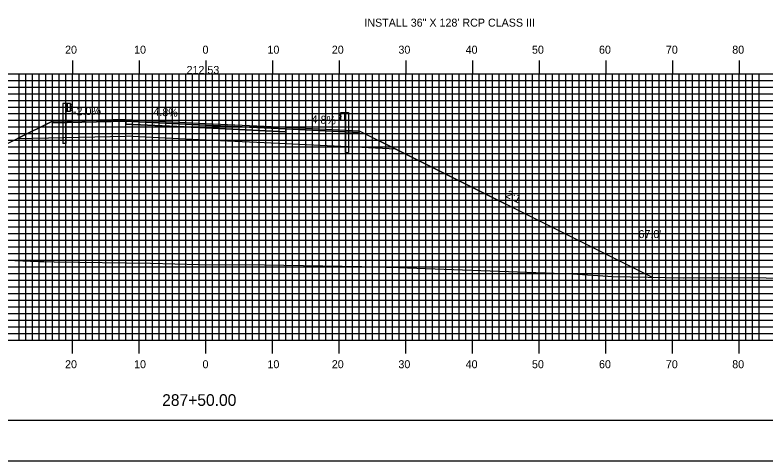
# Model space of a CAD drawing. Extents: x 1812948 to 1813291, y 442591 to 442811.
# Drawn here: x 1813084.9 to 1813197.3, y 442590.5 to 442657.5 of the extents above; entities that cross this region are included whole.
import ezdxf

# ---------------------------------------------------------------- set-up
doc = ezdxf.new("R2010")
doc.units = 0
for name, color, linetype in [('ANNOTATION', 7, 'Continuous'), ('BORDER', 7, 'Continuous'), ('D_Guardrail_Beam_Lt', 7, 'Continuous'), ('D_Guardrail_Beam_Rt', 7, 'Continuous'), ('D_Roadway_Centerline', 7, 'Continuous'), ('D_Roadway_Centerline_Text', 7, 'Continuous'), ('D_Roadway_Edge_Shoulder', 7, 'Continuous'), ('D_Roadway_Edge_TW', 7, 'Continuous'), ('D_Roadway_Pavement', 7, 'Continuous'), ('D_Roadway_SlopeLines', 7, 'Continuous'), ('D_Roadway_SubGrade', 7, 'Continuous'), ('D_Text_Standard', 7, 'Continuous'), ('H_V ANNOTATION', 7, 'Continuous'), ('MAJOR', 7, 'Continuous'), ('MINOR', 7, 'Continuous'), ('PLOT BOUNDARY', 7, 'Continuous'), ('S_Roadway_Centerline', 7, 'Continuous')]:
    doc.layers.add(name, color=color, linetype=linetype)

msp = doc.modelspace()

# ---------------------------------------------------------------- linework, layer by layer
at = {"layer": 'BORDER'}
msp.add_lwpolyline([(1812963.86, 442596.67), (1813283.86, 442596.67), (1813283.86, 442806.67), (1812963.86, 442806.67)], close=True, dxfattribs=at)
at = {"layer": 'D_Guardrail_Beam_Lt'}
for p, q in [((1813092.03, 442644.2), (1813092.03, 442638.2)), ((1813092.5, 442644.2), (1813092.03, 442644.2)), ((1813093.18, 442644.2), (1813092.5, 442644.2)), ((1813092.5, 442644.2), (1813092.5, 442643.03)), ((1813092.56, 442644.2), (1813092.56, 442643.03)), ((1813092.66, 442644.2), (1813092.66, 442643.03)), ((1813093.18, 442643.03), (1813093.18, 442644.2)), ((1813093.18, 442644.11), (1813093.26, 442644.1)), ((1813093.27, 442644.09), (1813093.42, 442643.99)), ((1813092.5, 442643.03), (1813093.18, 442643.03)), ((1813092.52, 442638.2), (1813092.52, 442643.03)), ((1813093.26, 442643.13), (1813093.18, 442643.11)), ((1813093.19, 442643.65), (1813093.19, 442643.58)), ((1813093.42, 442643.85), (1813093.22, 442643.71)), ((1813093.22, 442643.52), (1813093.42, 442643.38)), ((1813093.42, 442643.24), (1813093.27, 442643.14)), ((1813092.52, 442638.2), (1813092.03, 442638.2))]:
    msp.add_line(p, q, dxfattribs=at)
for centre, major_axis, start_param, end_param in [((1813093.25, 442644.06), (0.0417, 0), 0.959931, 1.376053), ((1813093.27, 442643.65), (-0.0789, 0), 5.323254, 6.283185), ((1813093.27, 442643.58), (-0.0789, 0), 6.283185, 7.243116), ((1813093.25, 442643.17), (0.0417, 0), 4.907132, 5.323254), ((1813093.37, 442643.92), (0.0877, 0), 5.323254, 7.243116), ((1813093.37, 442643.31), (0.0877, 0), 5.323254, 7.243116)]:
    msp.add_ellipse(centre, major_axis=major_axis, ratio=0.995501, start_param=start_param, end_param=end_param, dxfattribs=at)
at = {"layer": 'D_Guardrail_Beam_Rt'}
for p, q in [((1813133.64, 442642.72), (1813133.49, 442642.62)), ((1813133.49, 442642.47), (1813133.69, 442642.34)), ((1813133.69, 442642.14), (1813133.49, 442642)), ((1813133.49, 442641.86), (1813133.64, 442641.76)), ((1813133.73, 442642.74), (1813133.65, 442642.72)), ((1813133.65, 442641.75), (1813133.73, 442641.74)), ((1813133.72, 442642.27), (1813133.72, 442642.2)), ((1813133.73, 442642.82), (1813134.41, 442642.82)), ((1813133.73, 442641.66), (1813133.73, 442642.82)), ((1813134.25, 442642.82), (1813134.25, 442641.66)), ((1813134.35, 442642.82), (1813134.35, 442641.66)), ((1813134.41, 442642.82), (1813134.88, 442642.82)), ((1813134.41, 442642.82), (1813134.41, 442641.66)), ((1813134.88, 442642.82), (1813134.88, 442636.82)), ((1813134.41, 442641.66), (1813133.73, 442641.66)), ((1813134.39, 442636.82), (1813134.39, 442641.66)), ((1813134.39, 442636.82), (1813134.88, 442636.82))]:
    msp.add_line(p, q, dxfattribs=at)
for centre, major_axis, start_param, end_param in [((1813133.54, 442642.55), (-0.0877, 0), 5.323254, 7.243116), ((1813133.54, 442641.93), (-0.0877, 0), 5.323254, 7.243116), ((1813133.66, 442642.68), (-0.0417, 0), 4.907132, 5.323254), ((1813133.66, 442641.79), (-0.0417, 0), 0.959931, 1.376053), ((1813133.64, 442642.27), (0.0789, 0), 0, 0.959931), ((1813133.64, 442642.2), (0.0789, 0), 5.323254, 6.283185)]:
    msp.add_ellipse(centre, major_axis=major_axis, ratio=0.995501, start_param=start_param, end_param=end_param, dxfattribs=at)
at = {"layer": 'D_Roadway_Centerline'}
msp.add_lwpolyline([(1813053.59, 442623.12), (1813085.25, 442638.95), (1813090.46, 442641.55), (1813093.46, 442641.61), (1813101.46, 442641.77), (1813113.46, 442641.2), (1813125.46, 442640.62), (1813133.46, 442640.24), (1813136.46, 442640.09), (1813141.99, 442637.33), (1813180.41, 442618.12)], dxfattribs=at)
at = {"layer": 'D_Roadway_Edge_Shoulder'}
for points in [[(1813101.46, 442641.77), (1813093.46, 442641.61), (1813093.46, 442641.61), (1813090.46, 442641.55), (1813090.46, 442641.3), (1813101.46, 442641.52)], [(1813125.46, 442640.62), (1813133.46, 442640.24), (1813133.46, 442640.24), (1813136.46, 442640.09), (1813136.46, 442639.84), (1813125.46, 442640.37)]]:
    msp.add_lwpolyline(points, close=True, dxfattribs=at)
at = {"layer": 'D_Roadway_Edge_TW'}
msp.add_lwpolyline([(1813101.46, 442641.52), (1813101.46, 442641.77), (1813113.46, 442641.2), (1813125.46, 442640.62), (1813125.46, 442640.37), (1813113.46, 442640.95)], close=True, dxfattribs=at)
at = {"layer": 'D_Roadway_Pavement'}
msp.add_lwpolyline([(1813101.46, 442641.11), (1813101.46, 442641.52), (1813113.46, 442640.95), (1813125.46, 442640.37), (1813125.46, 442639.96), (1813113.46, 442640.53)], close=True, dxfattribs=at)
for points in [[(1813101.46, 442641.52), (1813101.46, 442641.11)], [(1813125.46, 442640.37), (1813125.46, 442639.96)]]:
    msp.add_lwpolyline(points, dxfattribs=at)
at = {"layer": 'D_Roadway_SlopeLines'}
for points in [[(1813090.46, 442641.55), (1813053.59, 442623.12)], [(1813136.46, 442640.09), (1813180.41, 442618.12)]]:
    msp.add_lwpolyline(points, dxfattribs=at)
at = {"layer": 'D_Roadway_SubGrade'}
for points in [[(1813101.46, 442641.11), (1813101.46, 442641.52), (1813090.46, 442641.3), (1813090.46, 442641.55), (1813085.25, 442638.95), (1813101.46, 442639.27)], [(1813101.46, 442639.27), (1813101.46, 442641.52), (1813101.46, 442641.11), (1813113.46, 442640.53), (1813125.46, 442639.96), (1813125.46, 442640.37), (1813125.46, 442638.12), (1813113.46, 442638.7)], [(1813125.46, 442639.96), (1813125.46, 442640.37), (1813136.46, 442639.84), (1813136.46, 442640.09), (1813141.99, 442637.33), (1813125.46, 442638.12)]]:
    msp.add_lwpolyline(points, close=True, dxfattribs=at)
at = {"layer": 'MAJOR'}
for p, q in [((1813093.46, 442650.67), (1813093.46, 442648.67)), ((1813103.46, 442650.67), (1813103.46, 442648.67)), ((1813113.46, 442650.67), (1813113.46, 442648.67)), ((1813123.46, 442650.67), (1813123.46, 442648.67)), ((1813133.46, 442650.67), (1813133.46, 442648.67)), ((1813143.46, 442650.67), (1813143.46, 442648.67)), ((1813153.46, 442650.67), (1813153.46, 442648.67)), ((1813163.46, 442650.67), (1813163.46, 442648.67)), ((1813173.46, 442650.67), (1813173.46, 442648.67)), ((1813183.46, 442650.67), (1813183.46, 442648.67)), ((1813193.46, 442650.67), (1813193.46, 442648.67)), ((1812973.46, 442648.67), (1813253.46, 442648.67)), ((1812973.46, 442648.67), (1813253.46, 442648.67)), ((1813093.46, 442608.67), (1813093.46, 442648.67)), ((1813103.46, 442608.67), (1813103.46, 442648.67)), ((1813113.46, 442608.67), (1813113.46, 442648.67)), ((1813123.46, 442608.67), (1813123.46, 442648.67)), ((1813133.46, 442608.67), (1813133.46, 442648.67)), ((1813143.46, 442608.67), (1813143.46, 442648.67)), ((1813153.46, 442608.67), (1813153.46, 442648.67)), ((1813163.46, 442608.67), (1813163.46, 442648.67)), ((1813173.46, 442608.67), (1813173.46, 442648.67)), ((1813183.46, 442608.67), (1813183.46, 442648.67)), ((1813193.46, 442608.67), (1813193.46, 442648.67)), ((1812973.46, 442643.67), (1813253.46, 442643.67)), ((1812973.46, 442638.67), (1813253.46, 442638.67)), ((1812973.46, 442633.67), (1813253.46, 442633.67)), ((1812973.46, 442628.67), (1813253.46, 442628.67)), ((1812973.46, 442623.67), (1813253.46, 442623.67)), ((1812973.46, 442618.67), (1813253.46, 442618.67)), ((1812973.46, 442613.67), (1813253.46, 442613.67)), ((1812973.46, 442608.67), (1813253.46, 442608.67)), ((1812973.46, 442608.67), (1813253.46, 442608.67)), ((1813093.46, 442606.66), (1813093.46, 442608.67)), ((1813103.46, 442606.66), (1813103.46, 442608.67)), ((1813113.46, 442606.66), (1813113.46, 442608.67)), ((1813123.46, 442606.66), (1813123.46, 442608.67)), ((1813133.46, 442606.66), (1813133.46, 442608.67)), ((1813143.46, 442606.66), (1813143.46, 442608.67)), ((1813153.46, 442606.66), (1813153.46, 442608.67)), ((1813163.46, 442606.66), (1813163.46, 442608.67)), ((1813173.46, 442606.66), (1813173.46, 442608.67)), ((1813183.46, 442606.66), (1813183.46, 442608.67)), ((1813193.46, 442606.66), (1813193.46, 442608.67))]:
    msp.add_line(p, q, dxfattribs=at)
at = {"layer": 'MINOR'}
for p, q in [((1813085.46, 442608.67), (1813085.46, 442648.67)), ((1813086.46, 442608.67), (1813086.46, 442648.67)), ((1813087.46, 442608.67), (1813087.46, 442648.67)), ((1813088.46, 442608.67), (1813088.46, 442648.67)), ((1813089.46, 442608.67), (1813089.46, 442648.67)), ((1813090.46, 442608.67), (1813090.46, 442648.67)), ((1813091.46, 442608.67), (1813091.46, 442648.67)), ((1813092.46, 442608.67), (1813092.46, 442648.67)), ((1813094.46, 442608.67), (1813094.46, 442648.67)), ((1813095.46, 442608.67), (1813095.46, 442648.67)), ((1813096.46, 442608.67), (1813096.46, 442648.67)), ((1813097.46, 442608.67), (1813097.46, 442648.67)), ((1813098.46, 442608.67), (1813098.46, 442648.67)), ((1813099.46, 442608.67), (1813099.46, 442648.67)), ((1813100.46, 442608.67), (1813100.46, 442648.67)), ((1813101.46, 442608.67), (1813101.46, 442648.67)), ((1813102.46, 442608.67), (1813102.46, 442648.67)), ((1813104.46, 442608.67), (1813104.46, 442648.67)), ((1813105.46, 442608.67), (1813105.46, 442648.67)), ((1813106.46, 442608.67), (1813106.46, 442648.67)), ((1813107.46, 442608.67), (1813107.46, 442648.67)), ((1813108.46, 442608.67), (1813108.46, 442648.67)), ((1813109.46, 442608.67), (1813109.46, 442648.67)), ((1813110.46, 442608.67), (1813110.46, 442648.67)), ((1813111.46, 442608.67), (1813111.46, 442648.67)), ((1813112.46, 442608.67), (1813112.46, 442648.67)), ((1813114.46, 442608.67), (1813114.46, 442648.67)), ((1813115.46, 442608.67), (1813115.46, 442648.67)), ((1813116.46, 442608.67), (1813116.46, 442648.67)), ((1813117.46, 442608.67), (1813117.46, 442648.67)), ((1813118.46, 442608.67), (1813118.46, 442648.67)), ((1813119.46, 442608.67), (1813119.46, 442648.67)), ((1813120.46, 442608.67), (1813120.46, 442648.67)), ((1813121.46, 442608.67), (1813121.46, 442648.67)), ((1813122.46, 442608.67), (1813122.46, 442648.67)), ((1813124.46, 442608.67), (1813124.46, 442648.67)), ((1813125.46, 442608.67), (1813125.46, 442648.67)), ((1813126.46, 442608.67), (1813126.46, 442648.67)), ((1813127.46, 442608.67), (1813127.46, 442648.67)), ((1813128.46, 442608.67), (1813128.46, 442648.67)), ((1813129.46, 442608.67), (1813129.46, 442648.67)), ((1813130.46, 442608.67), (1813130.46, 442648.67)), ((1813131.46, 442608.67), (1813131.46, 442648.67)), ((1813132.46, 442608.67), (1813132.46, 442648.67)), ((1813134.46, 442608.67), (1813134.46, 442648.67)), ((1813135.46, 442608.67), (1813135.46, 442648.67)), ((1813136.46, 442608.67), (1813136.46, 442648.67)), ((1813137.46, 442608.67), (1813137.46, 442648.67)), ((1813138.46, 442608.67), (1813138.46, 442648.67)), ((1813139.46, 442608.67), (1813139.46, 442648.67)), ((1813140.46, 442608.67), (1813140.46, 442648.67)), ((1813141.46, 442608.67), (1813141.46, 442648.67)), ((1813142.46, 442608.67), (1813142.46, 442648.67)), ((1813144.46, 442608.67), (1813144.46, 442648.67)), ((1813145.46, 442608.67), (1813145.46, 442648.67)), ((1813146.46, 442608.67), (1813146.46, 442648.67)), ((1813147.46, 442608.67), (1813147.46, 442648.67)), ((1813148.46, 442608.67), (1813148.46, 442648.67)), ((1813149.46, 442608.67), (1813149.46, 442648.67)), ((1813150.46, 442608.67), (1813150.46, 442648.67)), ((1813151.46, 442608.67), (1813151.46, 442648.67)), ((1813152.46, 442608.67), (1813152.46, 442648.67)), ((1813154.46, 442608.67), (1813154.46, 442648.67)), ((1813155.46, 442608.67), (1813155.46, 442648.67)), ((1813156.46, 442608.67), (1813156.46, 442648.67)), ((1813157.46, 442608.67), (1813157.46, 442648.67)), ((1813158.46, 442608.67), (1813158.46, 442648.67)), ((1813159.46, 442608.67), (1813159.46, 442648.67)), ((1813160.46, 442608.67), (1813160.46, 442648.67)), ((1813161.46, 442608.67), (1813161.46, 442648.67)), ((1813162.46, 442608.67), (1813162.46, 442648.67)), ((1813164.46, 442608.67), (1813164.46, 442648.67)), ((1813165.46, 442608.67), (1813165.46, 442648.67)), ((1813166.46, 442608.67), (1813166.46, 442648.67)), ((1813167.46, 442608.67), (1813167.46, 442648.67)), ((1813168.46, 442608.67), (1813168.46, 442648.67)), ((1813169.46, 442608.67), (1813169.46, 442648.67)), ((1813170.46, 442608.67), (1813170.46, 442648.67)), ((1813171.46, 442608.67), (1813171.46, 442648.67)), ((1813172.46, 442608.67), (1813172.46, 442648.67)), ((1813174.46, 442608.67), (1813174.46, 442648.67)), ((1813175.46, 442608.67), (1813175.46, 442648.67)), ((1813176.46, 442608.67), (1813176.46, 442648.67)), ((1813177.46, 442608.67), (1813177.46, 442648.67)), ((1813178.46, 442608.67), (1813178.46, 442648.67)), ((1813179.46, 442608.67), (1813179.46, 442648.67)), ((1813180.46, 442608.67), (1813180.46, 442648.67)), ((1813181.46, 442608.67), (1813181.46, 442648.67)), ((1813182.46, 442608.67), (1813182.46, 442648.67)), ((1813184.46, 442608.67), (1813184.46, 442648.67)), ((1813185.46, 442608.67), (1813185.46, 442648.67)), ((1813186.46, 442608.67), (1813186.46, 442648.67)), ((1813187.46, 442608.67), (1813187.46, 442648.67)), ((1813188.46, 442608.67), (1813188.46, 442648.67)), ((1813189.46, 442608.67), (1813189.46, 442648.67)), ((1813190.46, 442608.67), (1813190.46, 442648.67)), ((1813191.46, 442608.67), (1813191.46, 442648.67)), ((1813192.46, 442608.67), (1813192.46, 442648.67)), ((1813194.46, 442608.67), (1813194.46, 442648.67)), ((1813195.46, 442608.67), (1813195.46, 442648.67)), ((1813196.46, 442608.67), (1813196.46, 442648.67)), ((1812973.46, 442647.67), (1813253.46, 442647.67)), ((1812973.46, 442646.67), (1813253.46, 442646.67)), ((1812973.46, 442645.67), (1813253.46, 442645.67)), ((1812973.46, 442644.67), (1813253.46, 442644.67)), ((1812973.46, 442642.67), (1813253.46, 442642.67)), ((1812973.46, 442641.67), (1813253.46, 442641.67)), ((1812973.46, 442640.67), (1813253.46, 442640.67)), ((1812973.46, 442639.67), (1813253.46, 442639.67)), ((1812973.46, 442637.67), (1813253.46, 442637.67)), ((1812973.46, 442636.67), (1813253.46, 442636.67)), ((1812973.46, 442635.67), (1813253.46, 442635.67)), ((1812973.46, 442634.67), (1813253.46, 442634.67)), ((1812973.46, 442632.67), (1813253.46, 442632.67)), ((1812973.46, 442631.67), (1813253.46, 442631.67)), ((1812973.46, 442630.67), (1813253.46, 442630.67)), ((1812973.46, 442629.67), (1813253.46, 442629.67)), ((1812973.46, 442627.67), (1813253.46, 442627.67)), ((1812973.46, 442626.67), (1813253.46, 442626.67)), ((1812973.46, 442625.67), (1813253.46, 442625.67)), ((1812973.46, 442624.67), (1813253.46, 442624.67)), ((1812973.46, 442622.67), (1813253.46, 442622.67)), ((1812973.46, 442621.67), (1813253.46, 442621.67)), ((1812973.46, 442620.67), (1813253.46, 442620.67)), ((1812973.46, 442619.67), (1813253.46, 442619.67)), ((1812973.46, 442617.67), (1813253.46, 442617.67)), ((1812973.46, 442616.67), (1813253.46, 442616.67)), ((1812973.46, 442615.67), (1813253.46, 442615.67)), ((1812973.46, 442614.67), (1813253.46, 442614.67)), ((1812973.46, 442612.67), (1813253.46, 442612.67)), ((1812973.46, 442611.67), (1813253.46, 442611.67)), ((1812973.46, 442610.67), (1813253.46, 442610.67)), ((1812973.46, 442609.67), (1813253.46, 442609.67))]:
    msp.add_line(p, q, dxfattribs=at)
at = {"layer": 'PLOT BOUNDARY'}
msp.add_lwpolyline([(1812947.67, 442590.55), (1813287.67, 442590.55), (1813287.67, 442810.55), (1812947.67, 442810.55)], close=True, dxfattribs=at)
at = {"layer": 'S_Roadway_Centerline'}
msp.add_lwpolyline([(1813084.84, 442620.64), (1813088.36, 442620.5), (1813089.18, 442620.47), (1813090.73, 442620.43), (1813105.15, 442620.24), (1813112.48, 442620.04), (1813122.27, 442620.01), (1813139.78, 442619.7), (1813140.48, 442619.66), (1813141.1, 442619.66), (1813142.38, 442619.6), (1813168.45, 442618.61), (1813174.52, 442618.21), (1813185.03, 442618.05), (1813190.81, 442618.09), (1813204.22, 442618), (1813206.3, 442618.12), (1813207.36, 442618.02), (1813208.86, 442617.96), (1813224.42, 442617.68), (1813231.94, 442617.86), (1813241.21, 442617.57), (1813253.46, 442617.74)], dxfattribs=at)

# ---------------------------------------------------------------- texts
at = {"layer": 'ANNOTATION'}
for s, rotation, p in [('-2.0%', 1.1458, (1813093.56, 442642.42)), ('4.8%', 357.2519, (1813105.58, 442642.38)), ('-4.8%', 357.2519, (1813128.76, 442641.27)), ('2:1', 333.4349, (1813158.36, 442630.18))]:
    msp.add_text(s, height=1.2, rotation=rotation, dxfattribs=at).set_placement(p)
at = {"layer": 'D_Roadway_Centerline'}
for s, p in [('C', (1813113.45, 442641.2)), ('L', (1813113.46, 442641.19))]:
    msp.add_text(s, height=0.0146, dxfattribs=at).set_placement(p)
at = {"layer": 'D_Roadway_Centerline_Text'}
msp.add_text('212.53', height=1.2, dxfattribs=at).set_placement((1813110.58, 442648.63))
at = {"layer": 'D_Text_Standard'}
for s, p in [('INSTALL 36" X 128\' RCP CLASS III', (1813137.24, 442655.73)), ("67.0'", (1813178.35, 442624))]:
    msp.add_text(s, height=1.2, dxfattribs=at).set_placement(p)
at = {"layer": 'H_V ANNOTATION'}
for s, height, p in [('20', 1.2, (1813092.36, 442651.67)), ('10', 1.2, (1813102.71, 442651.67)), ('0', 1.2, (1813112.97, 442651.67)), ('10', 1.2, (1813122.71, 442651.67)), ('20', 1.2, (1813132.36, 442651.67)), ('30', 1.2, (1813142.35, 442651.67)), ('40', 1.2, (1813152.43, 442651.67)), ('50', 1.2, (1813162.38, 442651.67)), ('60', 1.2, (1813172.43, 442651.67)), ('70', 1.2, (1813182.46, 442651.67)), ('80', 1.2, (1813192.41, 442651.67)), ('20', 1.2, (1813092.36, 442604.47)), ('10', 1.2, (1813102.71, 442604.47)), ('0', 1.2, (1813112.97, 442604.47)), ('10', 1.2, (1813122.71, 442604.47)), ('20', 1.2, (1813132.36, 442604.47)), ('30', 1.2, (1813142.35, 442604.47)), ('40', 1.2, (1813152.43, 442604.47)), ('50', 1.2, (1813162.38, 442604.47)), ('60', 1.2, (1813172.43, 442604.47)), ('70', 1.2, (1813182.46, 442604.47)), ('80', 1.2, (1813192.41, 442604.47)), ('287+50.00', 1.75, (1813106.92, 442598.82))]:
    msp.add_text(s, height=height, dxfattribs=at).set_placement(p)

doc.saveas('drawing.dxf')
